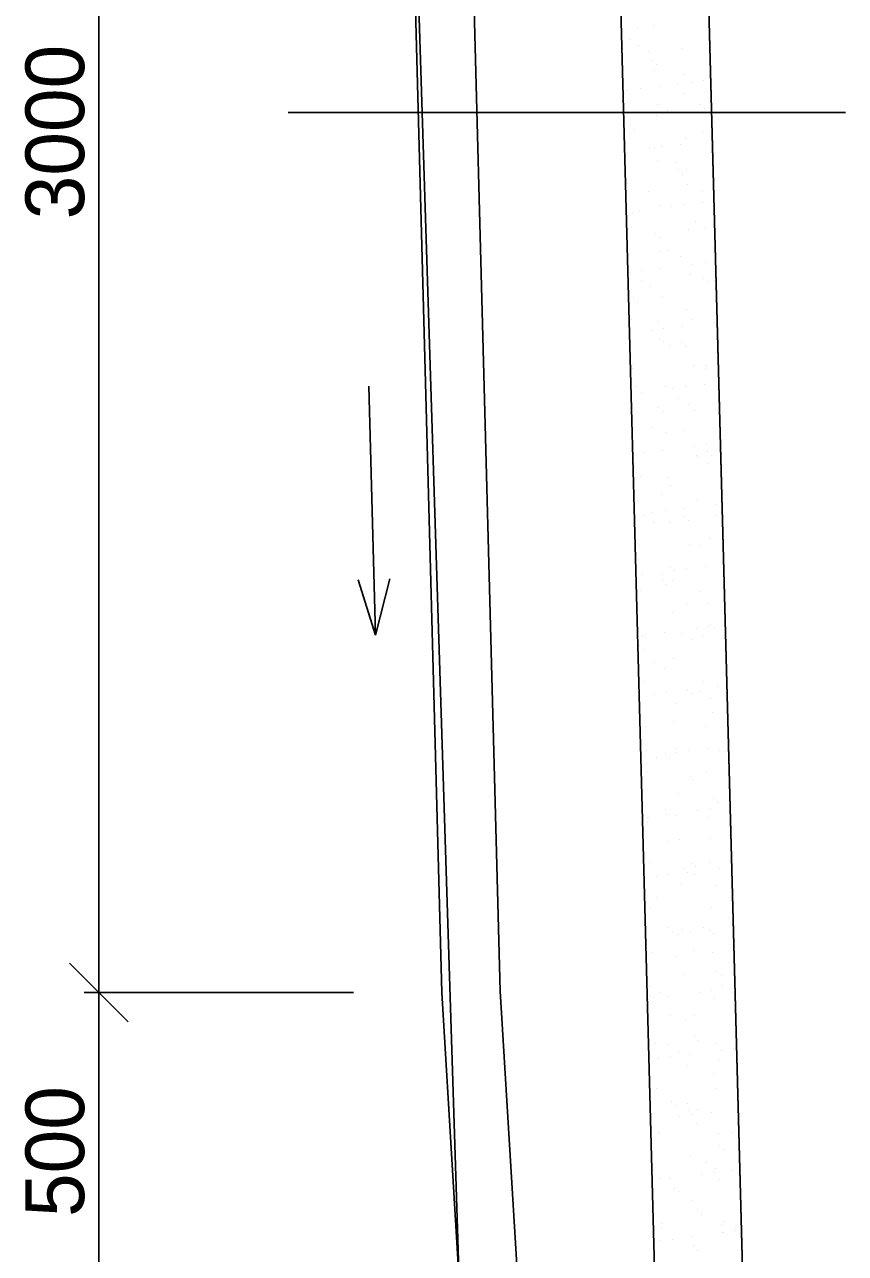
# Model space of a CAD drawing. Extents: x -2363 to 18637, y 14070 to 28920.
# Drawn here: x -595 to 804, y 21895 to 23989 of the extents above; entities that cross this region are included whole.
import ezdxf

# ---------------------------------------------------------------- set-up
doc = ezdxf.new("R2010")
doc.units = 0
for name, color, linetype in [('KÓTY', 7, 'Continuous'), ('OBRYS', 7, 'Continuous'), ('SJEZD', 7, 'Continuous'), ('ŠRAFY', 7, 'Continuous')]:
    doc.layers.add(name, color=color, linetype=linetype)

# ---------------------------------------------------------------- blocks, each defined once
blk = doc.blocks.new('_ARCHTICK')
blk.add_lwpolyline([(-0.5, -0.5), (0.5, 0.5)])

msp = doc.modelspace()

# ---------------------------------------------------------------- linework, layer by layer
at = {"layer": 'KÓTY'}
for p, q in [((-468.1, 22314.7), (-468.1, 25364.7)), ((-7.8, 23373.2), (3.6, 22948.8)), ((3.6, 22948.8), (-25.9, 23043.3)), ((3.6, 22948.8), (28, 23044.7)), ((-468.1, 21814.7), (-468.1, 22364.7)), ((-33.8, 22339.7), (-493.1, 22339.7)), ((-33.8, 22339.7), (-493.1, 22339.7))]:
    msp.add_line(p, q, dxfattribs=at)
at = {"layer": 'OBRYS'}
for p, q in [((649.6, 21092.9), (495.9, 26839.7)), ((146.2, 21839.7), (35.9, 25339.7))]:
    msp.add_line(p, q, dxfattribs=at)
at = {"layer": 'SJEZD'}
for p, q in [((495.9, 26839.7), (649.6, 21092.9)), ((375.9, 25715.5), (493.5, 21318.7)), ((35.9, 25339.7), (116.2, 22339.7)), ((135.9, 25338.9), (216.1, 22342)), ((-145.6, 23839.7), (804.2, 23839.7)), ((116.2, 22339.7), (146.2, 21839.7)), ((216.1, 22342), (246.2, 21839.7))]:
    msp.add_line(p, q, dxfattribs=at)
at = {"layer": 'ŠRAFY'}
for p, q in [((450, 23983), (450, 23983)), ((476.6, 23988.6), (476.6, 23988.6)), ((435.7, 23964.6), (435.7, 23964.6)), ((425, 23949.1), (425, 23949.1)), ((451.2, 23954.2), (451.2, 23954.2)), ((468.1, 23943.4), (468.1, 23943.4)), ((527.4, 23948.6), (527.4, 23948.6)), ((475.5, 23928.1), (475.5, 23928.1)), ((482.9, 23921.4), (482.9, 23921.4)), ((479.1, 23911.6), (479.1, 23911.6)), ((528.8, 23904.7), (528.8, 23904.7)), ((433.5, 23877.3), (433.5, 23877.3)), ((454.3, 23880), (454.3, 23880)), ((486.8, 23884.3), (486.8, 23884.3)), ((517.7, 23889.5), (517.7, 23889.5)), ((541.2, 23891.4), (541.2, 23891.4)), ((562, 23894.2), (562, 23894.2)), ((427.6, 23872), (427.6, 23872)), ((529.9, 23871.5), (529.9, 23871.5)), ((481.7, 23834.5), (481.7, 23834.5)), ((483.5, 23854), (483.5, 23854)), ((500.4, 23843.2), (500.4, 23843.2)), ((557.5, 23853), (557.5, 23853)), ((564.9, 23846.2), (564.9, 23846.2)), ((437.3, 23817.9), (437.3, 23817.9)), ((430.1, 23794.9), (430.1, 23794.9)), ((436.5, 23804.3), (436.5, 23804.3)), ((444.6, 23811.1), (444.6, 23811.1)), ((532.4, 23794.4), (532.4, 23794.4)), ((561.1, 23804.6), (561.1, 23804.6)), ((470.4, 23778.5), (470.4, 23778.5)), ((479.4, 23779.3), (479.4, 23779.3)), ((491.2, 23781.3), (491.2, 23781.3)), ((523.7, 23785.6), (523.7, 23785.6)), ((484.2, 23757.4), (484.2, 23757.4)), ((515.8, 23753.8), (515.8, 23753.8)), ((519.2, 23742.8), (519.2, 23742.8)), ((526.6, 23736), (526.6, 23736)), ((532.7, 23743.1), (532.7, 23743.1)), ((432.6, 23717.8), (432.6, 23717.8)), ((534.9, 23717.4), (534.9, 23717.4)), ((468.8, 23704.2), (468.8, 23704.2)), ((561.4, 23704.1), (561.4, 23704.1)), ((441.2, 23669), (441.2, 23669)), ((452.9, 23672.7), (452.9, 23672.7)), ((486.7, 23680.3), (486.7, 23680.3)), ((507.3, 23679.8), (507.3, 23679.8)), ((528.1, 23682.6), (528.1, 23682.6)), ((560.6, 23686.9), (560.6, 23686.9)), ((548.1, 23653.7), (548.1, 23653.7)), ((435.1, 23640.8), (435.1, 23640.8)), ((440.4, 23642.7), (440.4, 23642.7)), ((481, 23632.5), (481, 23632.5)), ((488.4, 23625.8), (488.4, 23625.8)), ((537.4, 23640.3), (537.4, 23640.3)), ((565, 23642.9), (565, 23642.9)), ((501.1, 23604), (501.1, 23604)), ((489.2, 23603.3), (489.2, 23603.3)), ((523.2, 23593.9), (523.2, 23593.9)), ((565, 23583.9), (565, 23583.9)), ((436.5, 23566.9), (436.5, 23566.9)), ((437.6, 23563.7), (437.6, 23563.7)), ((457.3, 23569.7), (457.3, 23569.7)), ((489.8, 23574), (489.8, 23574)), ((540, 23563.2), (540, 23563.2)), ((544.1, 23581.1), (544.1, 23581.1)), ((455.9, 23553.3), (455.9, 23553.3)), ((472.7, 23542.5), (472.7, 23542.5)), ((563, 23557.4), (563, 23557.4)), ((570.3, 23550.7), (570.3, 23550.7)), ((580.4, 23553.5), (580.4, 23553.5)), ((442.7, 23522.3), (442.7, 23522.3)), ((491.7, 23526.2), (491.7, 23526.2)), ((450.1, 23515.6), (450.1, 23515.6)), ((533.5, 23503.8), (533.5, 23503.8)), ((440.2, 23486.6), (440.2, 23486.6)), ((484.9, 23483.7), (484.9, 23483.7)), ((542.5, 23486.1), (542.5, 23486.1)), ((581, 23482.4), (581, 23482.4)), ((473.3, 23468.2), (473.3, 23468.2)), ((494.2, 23471), (494.2, 23471)), ((526.7, 23475.3), (526.7, 23475.3)), ((488.2, 23453.1), (488.2, 23453.1)), ((494.3, 23449.1), (494.3, 23449.1)), ((505, 23442.4), (505, 23442.4)), ((524.7, 23447.2), (524.7, 23447.2)), ((532.1, 23440.4), (532.1, 23440.4)), ((441.2, 23403.5), (441.2, 23403.5)), ((442.7, 23409.6), (442.7, 23409.6)), ((545, 23409.1), (545, 23409.1)), ((565.8, 23403.7), (565.8, 23403.7)), ((566.9, 23408.5), (566.9, 23408.5)), ((446.6, 23373.4), (446.6, 23373.4)), ((563.6, 23376.6), (563.6, 23376.6)), ((455.9, 23362.4), (455.9, 23362.4)), ((496.8, 23372.1), (496.8, 23372.1)), ((510.2, 23369.5), (510.2, 23369.5)), ((520.5, 23352.9), (520.5, 23352.9)), ((531, 23372.3), (531, 23372.3)), ((445.2, 23332.5), (445.2, 23332.5)), ((486.4, 23336.9), (486.4, 23336.9)), ((537.3, 23342.2), (537.3, 23342.2)), ((547.5, 23332), (547.5, 23332)), ((493.8, 23330.2), (493.8, 23330.2)), ((473.5, 23303.3), (473.5, 23303.3)), ((499.3, 23295), (499.3, 23295)), ((528.6, 23298.3), (528.6, 23298.3)), ((547.1, 23270.8), (547.1, 23270.8)), ((567.9, 23273.6), (567.9, 23273.6)), ((447.7, 23255.4), (447.7, 23255.4)), ((460.3, 23259.4), (460.3, 23259.4)), ((492.8, 23263.7), (492.8, 23263.7)), ((550, 23254.9), (550, 23254.9)), ((552.8, 23252.8), (552.8, 23252.8)), ((568.4, 23261.8), (568.4, 23261.8)), ((575.8, 23255.1), (575.8, 23255.1)), ((445.1, 23241.8), (445.1, 23241.8)), ((448.2, 23226.7), (448.2, 23226.7)), ((569.6, 23242), (569.6, 23242)), ((455.6, 23220), (455.6, 23220)), ((501.8, 23217.9), (501.8, 23217.9)), ((490.4, 23188.1), (490.4, 23188.1)), ((505.8, 23203.1), (505.8, 23203.1)), ((450.2, 23178.3), (450.2, 23178.3)), ((529.7, 23165), (529.7, 23165)), ((552.6, 23177.8), (552.6, 23177.8)), ((584, 23172.1), (584, 23172.1)), ((460.5, 23152.4), (460.5, 23152.4)), ((476.3, 23157.9), (476.3, 23157.9)), ((497.1, 23160.7), (497.1, 23160.7)), ((530.2, 23151.6), (530.2, 23151.6)), ((537.5, 23144.8), (537.5, 23144.8)), ((585.1, 23152.6), (585.1, 23152.6)), ((477.4, 23141.6), (477.4, 23141.6)), ((504.3, 23140.8), (504.3, 23140.8)), ((452.8, 23101.3), (452.8, 23101.3)), ((538.1, 23103), (538.1, 23103)), ((572.3, 23112.9), (572.3, 23112.9)), ((555.1, 23100.8), (555.1, 23100.8)), ((452.1, 23077.8), (452.1, 23077.8)), ((506.9, 23063.8), (506.9, 23063.8)), ((513.2, 23059.2), (513.2, 23059.2)), ((534, 23062), (534, 23062)), ((566.5, 23066.2), (566.5, 23066.2)), ((458.9, 23052.1), (458.9, 23052.1)), ((491.9, 23041.4), (491.9, 23041.4)), ((492.8, 23052.2), (492.8, 23052.2)), ((509.7, 23041.5), (509.7, 23041.5)), ((455.3, 23024.2), (455.3, 23024.2)), ((499.3, 23034.6), (499.3, 23034.6)), ((557.6, 23023.7), (557.6, 23023.7)), ((534.1, 23002.7), (534.1, 23002.7)), ((570.4, 23002.8), (570.4, 23002.8)), ((509.4, 22986.7), (509.4, 22986.7)), ((550.1, 22960.5), (550.1, 22960.5)), ((570.9, 22963.3), (570.9, 22963.3)), ((573.9, 22966.2), (573.9, 22966.2)), ((581.3, 22959.5), (581.3, 22959.5)), ((457.8, 22947.1), (457.8, 22947.1)), ((463.2, 22949.1), (463.2, 22949.1)), ((495.7, 22953.4), (495.7, 22953.4)), ((525.1, 22952.1), (525.1, 22952.1)), ((542, 22941.3), (542, 22941.3)), ((560.1, 22946.6), (560.1, 22946.6)), ((453.7, 22931.1), (453.7, 22931.1)), ((461, 22924.4), (461, 22924.4)), ((478.2, 22902.4), (478.2, 22902.4)), ((495.8, 22892.5), (495.8, 22892.5)), ((511.9, 22909.6), (511.9, 22909.6)), ((460.3, 22870), (460.3, 22870)), ((500.1, 22850.4), (500.1, 22850.4)), ((532.6, 22854.6), (532.6, 22854.6)), ((535.6, 22856), (535.6, 22856)), ((557.4, 22851.9), (557.4, 22851.9)), ((562.6, 22869.6), (562.6, 22869.6)), ((587, 22861.8), (587, 22861.8)), ((479.3, 22847.6), (479.3, 22847.6)), ((514.4, 22832.5), (514.4, 22832.5)), ((543, 22849.2), (543, 22849.2)), ((574.3, 22841.2), (574.3, 22841.2)), ((577.8, 22817.4), (577.8, 22817.4)), ((462.8, 22793), (462.8, 22793)), ((510.5, 22802.2), (510.5, 22802.2)), ((565.2, 22792.5), (565.2, 22792.5)), ((457.6, 22782.2), (457.6, 22782.2)), ((465.2, 22751.5), (465.2, 22751.5)), ((497.4, 22745.8), (497.4, 22745.8)), ((516.2, 22748.9), (516.2, 22748.9)), ((516.9, 22755.5), (516.9, 22755.5)), ((537, 22751.7), (537, 22751.7)), ((569.5, 22755.9), (569.5, 22755.9)), ((589.7, 22751.7), (589.7, 22751.7)), ((461.8, 22741.8), (461.8, 22741.8)), ((482, 22740.8), (482, 22740.8)), ((504.7, 22739), (504.7, 22739)), ((465.4, 22715.9), (465.4, 22715.9)), ((539.5, 22707.1), (539.5, 22707.1)), ((567.7, 22715.4), (567.7, 22715.4)), ((542.8, 22702.1), (542.8, 22702.1)), ((519.4, 22678.4), (519.4, 22678.4)), ((579.4, 22670.6), (579.4, 22670.6)), ((586.7, 22663.9), (586.7, 22663.9)), ((497.5, 22651.3), (497.5, 22651.3)), ((498.7, 22643), (498.7, 22643)), ((514.3, 22640.6), (514.3, 22640.6)), ((553, 22650.2), (553, 22650.2)), ((573.9, 22652.9), (573.9, 22652.9)), ((606.4, 22657.2), (606.4, 22657.2)), ((459.1, 22635.5), (459.1, 22635.5)), ((466.2, 22638.8), (466.2, 22638.8)), ((466.5, 22628.8), (466.5, 22628.8)), ((467.9, 22638.8), (467.9, 22638.8)), ((570.2, 22638.3), (570.2, 22638.3)), ((522, 22601.3), (522, 22601.3)), ((575.1, 22601.9), (575.1, 22601.9)), ((501.3, 22596.9), (501.3, 22596.9)), ((470.4, 22561.8), (470.4, 22561.8)), ((541.1, 22560.4), (541.1, 22560.4)), ((572.7, 22561.3), (572.7, 22561.3)), ((482.3, 22537.3), (482.3, 22537.3)), ((503.1, 22540.1), (503.1, 22540.1)), ((529.8, 22551.2), (529.8, 22551.2)), ((535.6, 22544.3), (535.6, 22544.3)), ((546.7, 22540.4), (546.7, 22540.4)), ((548.5, 22553.7), (548.5, 22553.7)), ((589.9, 22551.5), (589.9, 22551.5)), ((524.5, 22524.2), (524.5, 22524.2)), ((583.3, 22521.8), (583.3, 22521.8)), ((482.8, 22501.5), (482.8, 22501.5)), ((607.4, 22501.7), (607.4, 22501.7)), ((463, 22486.7), (463, 22486.7)), ((472.9, 22484.7), (472.9, 22484.7)), ((575.2, 22484.2), (575.2, 22484.2)), ((464.8, 22431.5), (464.8, 22431.5)), ((502.8, 22450.2), (502.8, 22450.2)), ((510.2, 22443.4), (510.2, 22443.4)), ((519.1, 22438.6), (519.1, 22438.6)), ((527, 22447.2), (527, 22447.2)), ((540, 22441.3), (540, 22441.3)), ((562.1, 22451), (562.1, 22451)), ((572.5, 22445.6), (572.5, 22445.6)), ((579, 22440.3), (579, 22440.3)), ((545, 22411.5), (545, 22411.5)), ((475.4, 22407.6), (475.4, 22407.6)), ((515.1, 22401.4), (515.1, 22401.4)), ((577.8, 22407.1), (577.8, 22407.1)), ((529.5, 22370.1), (529.5, 22370.1)), ((584.8, 22375.1), (584.8, 22375.1)), ((592.2, 22368.3), (592.2, 22368.3)), ((469.8, 22350.6), (469.8, 22350.6)), ((594.4, 22350.9), (594.4, 22350.9)), ((609.4, 22346.9), (609.4, 22346.9)), ((469.2, 22328.5), (469.2, 22328.5)), ((472, 22333.2), (472, 22333.2)), ((478, 22330.5), (478, 22330.5)), ((486.7, 22339.9), (486.7, 22339.9)), ((501.7, 22332.7), (501.7, 22332.7)), ((556, 22339.9), (556, 22339.9)), ((576.8, 22342.6), (576.8, 22342.6)), ((580.3, 22330), (580.3, 22330)), ((611.3, 22340.1), (611.3, 22340.1)), ((506.8, 22301.3), (506.8, 22301.3)), ((532, 22293), (532, 22293)), ((547.4, 22301.2), (547.4, 22301.2)), ((546.6, 22264.8), (546.6, 22264.8)), ((480.5, 22253.5), (480.5, 22253.5)), ((502.1, 22250.5), (502.1, 22250.5)), ((553.9, 22258.1), (553.9, 22258.1)), ((582.8, 22253), (582.8, 22253)), ((613.7, 22243.9), (613.7, 22243.9)), ((485.2, 22227), (485.2, 22227)), ((506, 22229.8), (506, 22229.8)), ((519, 22239.7), (519, 22239.7)), ((538.6, 22234), (538.6, 22234)), ((588.7, 22226.2), (588.7, 22226.2)), ((592.9, 22241.2), (592.9, 22241.2)), ((534.6, 22216), (534.6, 22216)), ((579.7, 22201), (579.7, 22201)), ((483, 22176.4), (483, 22176.4)), ((585.3, 22175.9), (585.3, 22175.9)), ((508.3, 22154.6), (508.3, 22154.6)), ((515.7, 22147.8), (515.7, 22147.8)), ((534.4, 22150.3), (534.4, 22150.3)), ((537.1, 22138.9), (537.1, 22138.9)), ((551.3, 22139.6), (551.3, 22139.6)), ((522.1, 22128.3), (522.1, 22128.3)), ((542.9, 22131), (542.9, 22131)), ((575.4, 22135.3), (575.4, 22135.3)), ((485.5, 22099.3), (485.5, 22099.3)), ((487.5, 22100.6), (487.5, 22100.6)), ((550.5, 22115.9), (550.5, 22115.9)), ((587.8, 22098.8), (587.8, 22098.8)), ((612, 22100.9), (612, 22100.9)), ((590.3, 22079.5), (590.3, 22079.5)), ((539.6, 22061.8), (539.6, 22061.8)), ((597.7, 22072.7), (597.7, 22072.7)), ((477.4, 22037.6), (477.4, 22037.6)), ((566.7, 22050.1), (566.7, 22050.1)), ((583.6, 22039.4), (583.6, 22039.4)), ((612.3, 22036.6), (612.3, 22036.6)), ((488, 22022.2), (488, 22022.2)), ((504.7, 22022.4), (504.7, 22022.4)), ((559, 22029.6), (559, 22029.6)), ((579.8, 22032.3), (579.8, 22032.3)), ((590.4, 22021.8), (590.4, 22021.8)), ((512.2, 22005.7), (512.2, 22005.7)), ((519.8, 22000.5), (519.8, 22000.5)), ((542.1, 21984.7), (542.1, 21984.7)), ((552, 21969.2), (552, 21969.2)), ((559.4, 21962.5), (559.4, 21962.5)), ((599, 21950), (599, 21950)), ((490.6, 21945.2), (490.6, 21945.2)), ((491.3, 21939), (491.3, 21939)), ((592.9, 21944.7), (592.9, 21944.7)), ((594.2, 21930.6), (594.2, 21930.6)), ((595.9, 21930.9), (595.9, 21930.9)), ((615.9, 21939.2), (615.9, 21939.2)), ((616.7, 21933.6), (616.7, 21933.6)), ((488.2, 21916.7), (488.2, 21916.7)), ((509, 21919.4), (509, 21919.4)), ((541.5, 21923.7), (541.5, 21923.7)), ((544.6, 21907.7), (544.6, 21907.7)), ((552.1, 21900.3), (552.1, 21900.3))]:
    msp.add_line(p, q, dxfattribs=at)

# ---------------------------------------------------------------- block references
at = {"layer": 'KÓTY', "xscale": 100, "yscale": 100}
for rotation in [90, -90.00000000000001]:
    msp.add_blockref('_ARCHTICK', (-468.1, 22339.7), dxfattribs=dict(at, rotation=rotation))

# ---------------------------------------------------------------- texts
at = {"layer": 'KÓTY'}
for s, p in [('3000', (-493.1, 23657.5)), ('500', (-493.1, 21957.1))]:
    msp.add_text(s, height=100, rotation=90, dxfattribs=at).set_placement(p)

doc.saveas('drawing.dxf')
